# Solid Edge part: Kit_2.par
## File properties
Sűrűség: 0,000 kg/m^3
Pontosság: 0,990
Author: ahadarics
Last saved by: psaghy
Revision: 78
Username: ahadarics
Dokumentum tartalom típus: 0
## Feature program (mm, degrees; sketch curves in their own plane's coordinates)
base feature "unnamed BaseFeature 1"
sketch for "Furat_1" plane through (0, 0, 37) normal (0, 0, 1) x-axis (0, -1, 0)
  hole centre (-19, 19) bore radius 2.4585
hole "Furat_1" nominal diameter 6 finite  VBottomAngle = 118 deg
sketch for "unnamed Hole 1" plane through (0, 0, 37) normal (0, 0, 1) x-axis (0, -1, 0)
  hole centre (-19, -19) bore radius 2.4585
hole "unnamed Hole 1" finite
sketch for "unnamed Hole 2" plane through (0, 0, 37) normal (0, 0, 1) x-axis (0, -1, 0)
  hole centre (19, -19) bore radius 2.4585
hole "unnamed Hole 2" finite
sketch for "unnamed Hole 3" plane through (0, 0, 37) normal (0, 0, 1) x-axis (0, -1, 0)
  hole centre (19, 19) bore radius 2.4585
hole "unnamed Hole 3" finite
pattern "unnamed Pattern 1" of "Furat_1", "unnamed Hole 1", "unnamed Hole 2", "unnamed Hole 3"
sketch for "Furat_5" plane through (27.25, 0, 19.2488) normal (1, 0, 0) x-axis (0, 0, -1)
  hole centre (-3.7512, 5) bore radius 5.7225
hole "Furat_5" nominal diameter 13.157 finite  ThreadDepth = 12 mm
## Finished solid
Body 1: solid body, 370 faces, 887 edges, 570 vertices, 3 internal voids.
  Faces by surface: plane 146, cylinder 97, cone 43, torus 38, spline 31, sphere 9, swept 6
  Edges by curve: line 365, circle 310, curve on surface 184, spline 28
Bounding box of the edges (mm; curved faces can reach further): 54.500 x 54.500 x 53.000, from (-27.25, -27.25, 6) to (27.25, 27.25, 59).
Cylindrical faces by radius (mm): R0.2344 x1, R0.4113 x1, R0.4771 x1, R0.5 x7, R0.5094 x1, R0.5226 x1, R0.5534 x1, R0.6836 x1, R0.7041 x1, R0.7049 x1, R0.7519 x1, R0.7795 x1, R0.7904 x1, R0.8051 x1, R0.824 x1, R0.8903 x1, R0.9421 x1, R0.9541 x2, R1 x12, R1.0216 x1, R1.0284 x1, R1.25 x1, R1.2857 x1, R2.4585 x8, R3 x4, R3.1 x4, R3.5 x1, R4.95 x1, R5 x7, R5.15 x4, R5.72 x1, R5.7225 x1, R7.5 x1, R8 x1, R8.25 x4, R8.3 x1, R8.4 x1, R8.4236 x1, R8.7 x1, R10 x2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
Conical faces (half-angle, radius in mm at the cone's reference point): 1.6538 deg R9.75 x1, 3.5477 deg R10.7454 x1, 5.762 deg R8.4 x1, 11.1239 deg R8.0056 x1, 15 deg R16.1406 x1, 15.3654 deg R8.7214 x1, 19.3654 deg R9.1921 x1, 25.0169 deg R12.31 x1, 29.0546 deg R23.75 x4, 30 deg R5.1443 x1, 30 deg R9.8557 x2, 30 deg R10.1443 x1, 30 deg R17 x1, 45 deg R2.75 x1, 45 deg R2.825 x1, 45 deg R3.25 x8, 45 deg R4.85 x8, 45 deg R6.72 x1, 45 deg R8.15 x2, 45 deg R13.25 x1, 59 deg R2.4585 x4
Toroidal faces (ring radius, tube radius in mm): R0.9686 r0.5 x1, R1.4708 r0.5006 x3, R3.3 r0.3 x4, R4.7 r0.3 x1, R4.95 r0.2 x4, R5.65 r0.5 x4, R8.3 r0.3 x1, R8.3085 r0.3 x1, R8.75 r0.5 x2, R9.4279 r0.25 x1, R9.5 r0.5 x1, R10.2464 r0.5 x1, R12.8 r0.2 x1, R14.5 r2 x1, R15.3663 r0.5 x1, R18 r0.5 x1, R22 r1 x3, R26.5 r1 x6, R27.7942 r0.5 x1
Spherical faces by radius (mm): R0.5 x3, R1 x6
Planar faces by outward normal: +x 26, +y 10, +z 32, -x 5, -y 9, -z 22, oblique 42
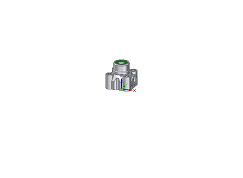
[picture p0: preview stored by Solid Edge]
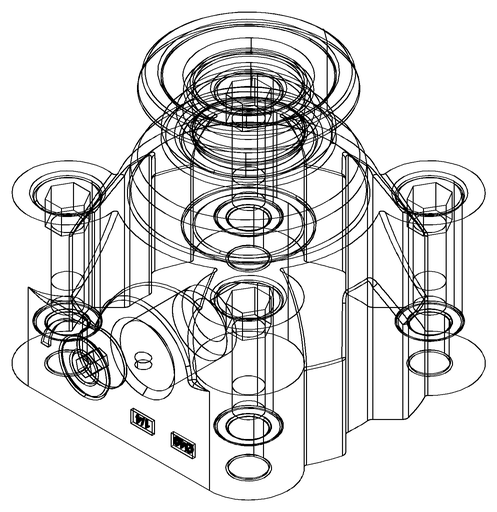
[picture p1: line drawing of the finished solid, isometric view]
